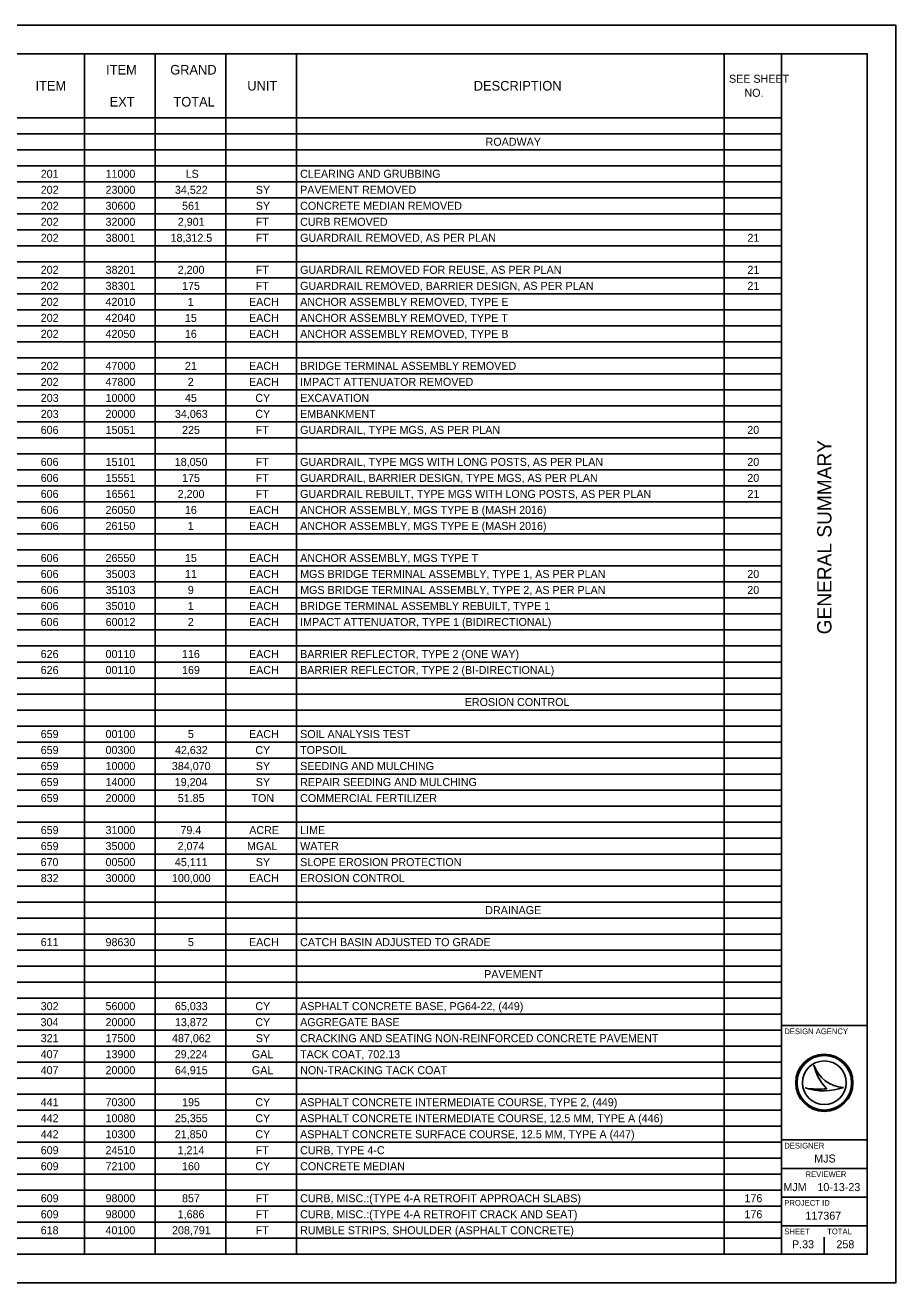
# Model space of a CAD drawing. Extents: x 0 to 34, y 0 to 22.
# Drawn here: x 18.78 to 34, y 0 to 22 of the extents above; entities that cross this region are included whole.
import ezdxf

# ---------------------------------------------------------------- set-up
doc = ezdxf.new("R2010")
doc.units = 0
for name, color, linetype in [('Default', 7, 'Continuous'), ('SH_Border', 7, 'Continuous'), ('SH_Cut_Line', 7, 'Continuous'), ('SH_Data', 7, 'Continuous')]:
    doc.layers.add(name, color=color, linetype=linetype)

msp = doc.modelspace()

# ---------------------------------------------------------------- linework, layer by layer
at = {"layer": 'Default'}
for p, q in [((1.5, 21.5), (32.004, 21.5)), ((19.815, 21.5), (19.815, 0.5)), ((21.051, 21.5), (21.051, 0.5)), ((22.286, 21.5), (22.286, 0.5)), ((23.521, 21.5), (23.521, 0.5)), ((30.999, 21.5), (30.999, 0.5)), ((32.004, 21.5), (32.004, 0.5)), ((1.5, 20.38), (32.004, 20.38)), ((1.5, 20.1), (32.004, 20.1)), ((1.5, 19.82), (32.004, 19.82)), ((1.5, 19.54), (32.004, 19.54)), ((1.5, 19.26), (32.004, 19.26)), ((1.5, 18.98), (32.004, 18.98)), ((1.5, 18.7), (32.004, 18.7)), ((1.5, 18.42), (32.004, 18.42)), ((1.5, 18.14), (32.004, 18.14)), ((1.5, 17.86), (32.004, 17.86)), ((1.5, 17.58), (32.004, 17.58)), ((1.5, 17.3), (32.004, 17.3)), ((1.5, 17.02), (32.004, 17.02)), ((1.5, 16.74), (32.004, 16.74)), ((1.5, 16.46), (32.004, 16.46)), ((1.5, 16.18), (32.004, 16.18)), ((1.5, 15.9), (32.004, 15.9)), ((1.5, 15.62), (32.004, 15.62)), ((1.5, 15.34), (32.004, 15.34)), ((1.5, 15.06), (32.004, 15.06)), ((1.5, 14.78), (32.004, 14.78)), ((1.5, 14.5), (32.004, 14.5)), ((1.5, 14.22), (32.004, 14.22)), ((1.5, 13.94), (32.004, 13.94)), ((1.5, 13.66), (32.004, 13.66)), ((1.5, 13.38), (32.004, 13.38)), ((1.5, 13.1), (32.004, 13.1)), ((1.5, 12.82), (32.004, 12.82)), ((1.5, 12.54), (32.004, 12.54)), ((1.5, 12.26), (32.004, 12.26)), ((1.5, 11.98), (32.004, 11.98)), ((1.5, 11.7), (32.004, 11.7)), ((1.5, 11.42), (32.004, 11.42)), ((1.5, 11.14), (32.004, 11.14)), ((1.5, 10.86), (32.004, 10.86)), ((1.5, 10.58), (32.004, 10.58)), ((1.5, 10.3), (32.004, 10.3)), ((1.5, 10.02), (32.004, 10.02)), ((1.5, 9.74), (32.004, 9.74)), ((1.5, 9.46), (32.004, 9.46)), ((1.5, 9.18), (32.004, 9.18)), ((1.5, 8.9), (32.004, 8.9)), ((1.5, 8.62), (32.004, 8.62)), ((1.5, 8.34), (32.004, 8.34)), ((1.5, 8.06), (32.004, 8.06)), ((1.5, 7.78), (32.004, 7.78)), ((1.5, 7.5), (32.004, 7.5)), ((1.5, 7.22), (32.004, 7.22)), ((1.5, 6.94), (32.004, 6.94)), ((1.5, 6.66), (32.004, 6.66)), ((1.5, 6.38), (32.004, 6.38)), ((1.5, 6.1), (32.004, 6.1)), ((1.5, 5.82), (32.004, 5.82)), ((1.5, 5.54), (32.004, 5.54)), ((1.5, 5.26), (32.004, 5.26)), ((1.5, 4.98), (32.004, 4.98)), ((1.5, 4.7), (32.004, 4.7)), ((1.5, 4.42), (32.004, 4.42)), ((1.5, 4.14), (32.004, 4.14)), ((1.5, 3.86), (32.004, 3.86)), ((1.5, 3.58), (32.004, 3.58)), ((1.5, 3.3), (32.004, 3.3)), ((1.5, 3.02), (32.004, 3.02)), ((1.5, 2.74), (32.004, 2.74)), ((1.5, 2.46), (32.004, 2.46)), ((1.5, 2.18), (32.004, 2.18)), ((1.5, 1.9), (32.004, 1.9)), ((1.5, 1.62), (32.004, 1.62)), ((1.5, 1.34), (32.004, 1.34)), ((1.5, 1.06), (32.004, 1.06)), ((1.5, 0.78), (32.004, 0.78)), ((1.5, 0.5), (32.004, 0.5))]:
    msp.add_line(p, q, dxfattribs=at)
at = {"layer": 'SH_Border'}
for p, q in [((32, 0.5), (32, 21.5)), ((32, 4.5), (33.5, 4.5)), ((32, 2.5), (33.5, 2.5)), ((32, 2), (33.5, 2)), ((32, 1.5), (33.5, 1.5)), ((32, 1), (33.5, 1))]:
    msp.add_line(p, q, dxfattribs=at)
msp.add_lwpolyline([(1.5, 21.5), (33.5, 21.5), (33.5, 0.5), (1.5, 0.5)], close=True, dxfattribs=at)
at = {"layer": 'SH_Cut_Line'}
msp.add_lwpolyline([(0, 0), (34, 0), (34, 22), (0, 22)], close=True, dxfattribs=at)
at = {"layer": 'SH_Data'}
for p, q in [((32.567, 3.81), (32.567, 3.81)), ((32.417, 3.41), (32.417, 3.41)), ((32.75, 3.5), (32.75, 3.5)), ((33.087, 3.419), (33.087, 3.419)), ((32.375, 0.675), (32.375, 0.675)), ((32.75, 0.5), (32.75, 0.8))]:
    msp.add_line(p, q, dxfattribs=at)
for radius in [0.5, 0.477, 0.477, 0.382]:
    msp.add_circle((32.75, 3.5), radius, dxfattribs=at)
for centre, radius, start, end in [((33.116, 3.998), 0.58, 198.9257, 198.9319), ((33.347, 3.97), 0.796, 191.6379, 191.6421), ((33.116, 3.998), 0.58, 198.9319, 267.1657), ((33.347, 3.97), 0.796, 191.6421, 226.0947), ((32.739, 4.37), 1.013, 251.4576, 290.0832), ((32.648, 4.654), 1.266, 259.4964, 259.4995), ((32.739, 4.37), 1.013, 251.4527, 251.4576), ((32.648, 4.654), 1.266, 259.4995, 276.6672)]:
    msp.add_arc(centre, radius, start, end, dxfattribs=at)

# ---------------------------------------------------------------- texts
at = {"layer": 'Default'}
for s, height, p in [('ITEM', 0.168, (20.195, 21.136)), ('GRAND', 0.168, (21.315, 21.136)), ('SEE SHEET ', 0.14, (31.084, 20.992)), ('ITEM', 0.168, (18.96, 20.856)), ('UNIT', 0.168, (22.663, 20.856)), ('DESCRIPTION', 0.168, (26.622, 20.856)), ('EXT', 0.168, (20.256, 20.576)), ('TOTAL', 0.168, (21.371, 20.576)), ('NO.', 0.14, (31.354, 20.747)), ('ROADWAY', 0.14, (26.829, 19.89)), ('201', 0.14, (19.052, 19.33)), ('11000', 0.14, (20.185, 19.33)), ('LS', 0.14, (21.585, 19.33)), ('CLEARING AND GRUBBING', 0.14, (23.587, 19.33)), ('202', 0.14, (19.052, 19.05)), ('23000', 0.14, (20.185, 19.05)), ('34,522', 0.14, (21.398, 19.05)), ('SY', 0.14, (22.812, 19.05)), ('PAVEMENT REMOVED', 0.14, (23.587, 19.05)), ('202', 0.14, (19.052, 18.77)), ('30600', 0.14, (20.185, 18.77)), ('561', 0.14, (21.523, 18.77)), ('SY', 0.14, (22.812, 18.77)), ('CONCRETE MEDIAN REMOVED', 0.14, (23.587, 18.77)), ('202', 0.14, (19.052, 18.49)), ('32000', 0.14, (20.185, 18.49)), ('2,901', 0.14, (21.448, 18.49)), ('FT', 0.14, (22.81, 18.49)), ('CURB REMOVED', 0.14, (23.587, 18.49)), ('202', 0.14, (19.052, 18.21)), ('38001', 0.14, (20.187, 18.21)), ('18,312.5', 0.14, (21.322, 18.21)), ('FT', 0.14, (22.81, 18.21)), ('GUARDRAIL REMOVED, AS PER PLAN', 0.14, (23.587, 18.21)), ('21', 0.14, (31.406, 18.21)), ('202', 0.14, (19.052, 17.65)), ('38201', 0.14, (20.187, 17.65)), ('2,200', 0.14, (21.446, 17.65)), ('FT', 0.14, (22.81, 17.65)), ('GUARDRAIL REMOVED FOR REUSE, AS PER PLAN', 0.14, (23.587, 17.65)), ('21', 0.14, (31.406, 17.65)), ('202', 0.14, (19.052, 17.37)), ('38301', 0.14, (20.187, 17.37)), ('175', 0.14, (21.523, 17.37)), ('FT', 0.14, (22.81, 17.37)), ('GUARDRAIL REMOVED, BARRIER DESIGN, AS PER PLAN', 0.14, (23.587, 17.37)), ('21', 0.14, (31.406, 17.37)), ('202', 0.14, (19.052, 17.09)), ('42010', 0.14, (20.185, 17.09)), ('1', 0.14, (21.623, 17.09)), ('EACH', 0.14, (22.693, 17.09)), ('ANCHOR ASSEMBLY REMOVED, TYPE E', 0.14, (23.587, 17.09)), ('202', 0.14, (19.052, 16.81)), ('42040', 0.14, (20.185, 16.81)), ('15', 0.14, (21.573, 16.81)), ('EACH', 0.14, (22.693, 16.81)), ('ANCHOR ASSEMBLY REMOVED, TYPE T', 0.14, (23.587, 16.81)), ('202', 0.14, (19.052, 16.53)), ('42050', 0.14, (20.185, 16.53)), ('16', 0.14, (21.572, 16.53)), ('EACH', 0.14, (22.693, 16.53)), ('ANCHOR ASSEMBLY REMOVED, TYPE B', 0.14, (23.587, 16.53)), ('202', 0.14, (19.052, 15.97)), ('47000', 0.14, (20.185, 15.97)), ('21', 0.14, (21.573, 15.97)), ('EACH', 0.14, (22.693, 15.97)), ('BRIDGE TERMINAL ASSEMBLY REMOVED', 0.14, (23.587, 15.97)), ('202', 0.14, (19.052, 15.69)), ('47800', 0.14, (20.185, 15.69)), ('2', 0.14, (21.623, 15.69)), ('EACH', 0.14, (22.693, 15.69)), ('IMPACT ATTENUATOR REMOVED', 0.14, (23.587, 15.69)), ('203', 0.14, (19.053, 15.41)), ('10000', 0.14, (20.185, 15.41)), ('45', 0.14, (21.573, 15.41)), ('CY', 0.14, (22.804, 15.41)), ('EXCAVATION', 0.14, (23.587, 15.41)), ('203', 0.14, (19.053, 15.13)), ('20000', 0.14, (20.185, 15.13)), ('34,063', 0.14, (21.398, 15.13)), ('CY', 0.14, (22.804, 15.13)), ('EMBANKMENT', 0.14, (23.587, 15.13)), ('606', 0.14, (19.051, 14.85)), ('15051', 0.14, (20.187, 14.85)), ('225', 0.14, (21.523, 14.85)), ('FT', 0.14, (22.81, 14.85)), ('GUARDRAIL, TYPE MGS, AS PER PLAN', 0.14, (23.587, 14.85)), ('20', 0.14, (31.404, 14.85)), ('606', 0.14, (19.051, 14.29)), ('15101', 0.14, (20.187, 14.29)), ('18,050', 0.14, (21.395, 14.29)), ('FT', 0.14, (22.81, 14.29)), ('GUARDRAIL, TYPE MGS WITH LONG POSTS, AS PER PLAN', 0.14, (23.587, 14.29)), ('20', 0.14, (31.404, 14.29)), ('606', 0.14, (19.051, 14.01)), ('15551', 0.14, (20.187, 14.01)), ('175', 0.14, (21.523, 14.01)), ('FT', 0.14, (22.81, 14.01)), ('GUARDRAIL, BARRIER DESIGN, TYPE MGS, AS PER PLAN', 0.14, (23.587, 14.01)), ('20', 0.14, (31.404, 14.01)), ('606', 0.14, (19.051, 13.73)), ('16561', 0.14, (20.187, 13.73)), ('2,200', 0.14, (21.446, 13.73)), ('FT', 0.14, (22.81, 13.73)), ('GUARDRAIL REBUILT, TYPE MGS WITH LONG POSTS, AS PER PLAN', 0.14, (23.587, 13.73)), ('21', 0.14, (31.406, 13.73)), ('606', 0.14, (19.051, 13.45)), ('26050', 0.14, (20.185, 13.45)), ('16', 0.14, (21.572, 13.45)), ('EACH', 0.14, (22.693, 13.45)), ('ANCHOR ASSEMBLY, MGS TYPE B (MASH 2016)', 0.14, (23.587, 13.45)), ('606', 0.14, (19.051, 13.17)), ('26150', 0.14, (20.185, 13.17)), ('1', 0.14, (21.623, 13.17)), ('EACH', 0.14, (22.693, 13.17)), ('ANCHOR ASSEMBLY, MGS TYPE E (MASH 2016)', 0.14, (23.587, 13.17)), ('606', 0.14, (19.051, 12.61)), ('26550', 0.14, (20.185, 12.61)), ('15', 0.14, (21.573, 12.61)), ('EACH', 0.14, (22.693, 12.61)), ('ANCHOR ASSEMBLY, MGS TYPE T', 0.14, (23.587, 12.61)), ('606', 0.14, (19.051, 12.33)), ('35003', 0.14, (20.188, 12.33)), ('11', 0.14, (21.573, 12.33)), ('EACH', 0.14, (22.693, 12.33)), ('MGS BRIDGE TERMINAL ASSEMBLY, TYPE 1, AS PER PLAN', 0.14, (23.587, 12.33)), ('20', 0.14, (31.404, 12.33)), ('606', 0.14, (19.051, 12.05)), ('35103', 0.14, (20.188, 12.05)), ('9', 0.14, (21.623, 12.05)), ('EACH', 0.14, (22.693, 12.05)), ('MGS BRIDGE TERMINAL ASSEMBLY, TYPE 2, AS PER PLAN', 0.14, (23.587, 12.05)), ('20', 0.14, (31.404, 12.05)), ('606', 0.14, (19.051, 11.77)), ('35010', 0.14, (20.185, 11.77)), ('1', 0.14, (21.623, 11.77)), ('EACH', 0.14, (22.693, 11.77)), ('BRIDGE TERMINAL ASSEMBLY REBUILT, TYPE 1', 0.14, (23.587, 11.77)), ('606', 0.14, (19.051, 11.49)), ('60012', 0.14, (20.187, 11.49)), ('2', 0.14, (21.623, 11.49)), ('EACH', 0.14, (22.693, 11.49)), ('IMPACT ATTENUATOR, TYPE 1 (BIDIRECTIONAL)', 0.14, (23.587, 11.49)), ('626', 0.14, (19.051, 10.93)), ('00110', 0.14, (20.185, 10.93)), ('116', 0.14, (21.521, 10.93)), ('EACH', 0.14, (22.693, 10.93)), ('BARRIER REFLECTOR, TYPE 2 (ONE WAY)', 0.14, (23.587, 10.93)), ('626', 0.14, (19.051, 10.65)), ('00110', 0.14, (20.185, 10.65)), ('169', 0.14, (21.522, 10.65)), ('EACH', 0.14, (22.693, 10.65)), ('BARRIER REFLECTOR, TYPE 2 (BI-DIRECTIONAL)', 0.14, (23.587, 10.65)), ('EROSION CONTROL', 0.14, (26.464, 10.09)), ('659', 0.14, (19.052, 9.53)), ('00100', 0.14, (20.185, 9.53)), ('5', 0.14, (21.624, 9.53)), ('EACH', 0.14, (22.693, 9.53)), ('SOIL ANALYSIS TEST', 0.14, (23.587, 9.53)), ('659', 0.14, (19.052, 9.25)), ('00300', 0.14, (20.185, 9.25)), ('42,632', 0.14, (21.398, 9.25)), ('CY', 0.14, (22.804, 9.25)), ('TOPSOIL', 0.14, (23.587, 9.25)), ('659', 0.14, (19.052, 8.97)), ('10000', 0.14, (20.185, 8.97)), ('384,070', 0.14, (21.345, 8.97)), ('SY', 0.14, (22.812, 8.97)), ('SEEDING AND MULCHING', 0.14, (23.587, 8.97)), ('659', 0.14, (19.052, 8.69)), ('14000', 0.14, (20.185, 8.69)), ('19,204', 0.14, (21.395, 8.69)), ('SY', 0.14, (22.812, 8.69)), ('REPAIR SEEDING AND MULCHING', 0.14, (23.587, 8.69)), ('659', 0.14, (19.052, 8.41)), ('20000', 0.14, (20.185, 8.41)), ('51.85', 0.14, (21.448, 8.41)), ('TON', 0.14, (22.737, 8.41)), ('COMMERCIAL FERTILIZER', 0.14, (23.587, 8.41)), ('659', 0.14, (19.052, 7.85)), ('31000', 0.14, (20.185, 7.85)), ('79.4', 0.14, (21.495, 7.85)), ('ACRE', 0.14, (22.697, 7.85)), ('LIME', 0.14, (23.587, 7.85)), ('659', 0.14, (19.052, 7.57)), ('35000', 0.14, (20.185, 7.57)), ('2,074', 0.14, (21.445, 7.57)), ('MGAL', 0.14, (22.658, 7.57)), ('WATER', 0.14, (23.587, 7.57)), ('670', 0.14, (19.05, 7.29)), ('00500', 0.14, (20.185, 7.29)), ('45,111', 0.14, (21.397, 7.29)), ('SY', 0.14, (22.812, 7.29)), ('SLOPE EROSION PROTECTION', 0.14, (23.587, 7.29)), ('832', 0.14, (19.052, 7.01)), ('30000', 0.14, (20.185, 7.01)), ('100,000', 0.14, (21.345, 7.01)), ('EACH', 0.14, (22.693, 7.01)), ('EROSION CONTROL', 0.14, (23.587, 7.01)), ('DRAINAGE', 0.14, (26.823, 6.45)), ('611', 0.14, (19.052, 5.89)), ('98630', 0.14, (20.185, 5.89)), ('5', 0.14, (21.624, 5.89)), ('EACH', 0.14, (22.693, 5.89)), ('CATCH BASIN ADJUSTED TO GRADE', 0.14, (23.587, 5.89)), ('PAVEMENT', 0.14, (26.803, 5.33)), ('302', 0.14, (19.052, 4.77)), ('56000', 0.14, (20.185, 4.77)), ('65,033', 0.14, (21.398, 4.77)), ('CY', 0.14, (22.804, 4.77)), ('ASPHALT CONCRETE BASE, PG64-22, (449)', 0.14, (23.587, 4.77)), ('304', 0.14, (19.05, 4.49)), ('20000', 0.14, (20.185, 4.49)), ('13,872', 0.14, (21.398, 4.49)), ('CY', 0.14, (22.804, 4.49)), ('AGGREGATE BASE', 0.14, (23.587, 4.49)), ('321', 0.14, (19.052, 4.21)), ('17500', 0.14, (20.185, 4.21)), ('487,062', 0.14, (21.347, 4.21)), ('SY', 0.14, (22.812, 4.21)), ('CRACKING AND SEATING NON-REINFORCED CONCRETE PAVEMENT', 0.14, (23.587, 4.21)), ('407', 0.14, (19.051, 3.93)), ('13900', 0.14, (20.185, 3.93)), ('29,224', 0.14, (21.395, 3.93)), ('GAL', 0.14, (22.743, 3.93)), ('TACK COAT, 702.13', 0.14, (23.587, 3.93)), ('407', 0.14, (19.051, 3.65)), ('20000', 0.14, (20.185, 3.65)), ('64,915', 0.14, (21.398, 3.65)), ('GAL', 0.14, (22.743, 3.65)), ('NON-TRACKING TACK COAT', 0.14, (23.587, 3.65)), ('441', 0.14, (19.052, 3.09)), ('70300', 0.14, (20.185, 3.09)), ('195', 0.14, (21.523, 3.09)), ('CY', 0.14, (22.804, 3.09)), ('ASPHALT CONCRETE INTERMEDIATE COURSE, TYPE 2, (449)', 0.14, (23.587, 3.09)), ('442', 0.14, (19.052, 2.81)), ('10080', 0.14, (20.185, 2.81)), ('25,355', 0.14, (21.398, 2.81)), ('CY', 0.14, (22.804, 2.81)), ('ASPHALT CONCRETE INTERMEDIATE COURSE, 12.5 MM, TYPE A (446)', 0.14, (23.587, 2.81)), ('442', 0.14, (19.052, 2.53)), ('10300', 0.14, (20.185, 2.53)), ('21,850', 0.14, (21.395, 2.53)), ('CY', 0.14, (22.804, 2.53)), ('ASPHALT CONCRETE SURFACE COURSE, 12.5 MM, TYPE A (447)', 0.14, (23.587, 2.53)), ('609', 0.14, (19.052, 2.25)), ('24510', 0.14, (20.185, 2.25)), ('1,214', 0.14, (21.445, 2.25)), ('FT', 0.14, (22.81, 2.25)), ('CURB, TYPE 4-C', 0.14, (23.587, 2.25)), ('609', 0.14, (19.052, 1.97)), ('72100', 0.14, (20.185, 1.97)), ('160', 0.14, (21.521, 1.97)), ('CY', 0.14, (22.804, 1.97)), ('CONCRETE MEDIAN', 0.14, (23.587, 1.97)), ('609', 0.14, (19.052, 1.41)), ('98000', 0.14, (20.185, 1.41)), ('857', 0.14, (21.522, 1.41)), ('FT', 0.14, (22.81, 1.41)), ('CURB, MISC.:(TYPE 4-A RETROFIT APPROACH SLABS)', 0.14, (23.587, 1.41)), ('176', 0.14, (31.354, 1.41)), ('609', 0.14, (19.052, 1.13)), ('98000', 0.14, (20.185, 1.13)), ('1,686', 0.14, (21.446, 1.13)), ('FT', 0.14, (22.81, 1.13)), ('CURB, MISC.:(TYPE 4-A RETROFIT CRACK AND SEAT)', 0.14, (23.587, 1.13)), ('176', 0.14, (31.354, 1.13)), ('618', 0.14, (19.051, 0.85)), ('40100', 0.14, (20.185, 0.85)), ('208,791', 0.14, (21.347, 0.85)), ('FT', 0.14, (22.81, 0.85)), ('RUMBLE STRIPS, SHOULDER (ASPHALT CONCRETE)', 0.14, (23.587, 0.85))]:
    msp.add_text(s, height=height, dxfattribs=at).set_placement(p)
at = {"layer": 'SH_Data'}
msp.add_text('GENERAL SUMMARY', height=0.25, rotation=90, dxfattribs=at).set_placement((32.875, 11.344))
for s, height, p in [('DESIGN AGENCY', 0.1, (32.05, 4.35)), ('DESIGNER', 0.1, (32.05, 2.35)), ('MJS', 0.14, (32.574, 2.105)), ('REVIEWER', 0.1, (32.422, 1.85)), ('MJM', 0.14, (32.035, 1.605)), ('10-13-23', 0.14, (32.629, 1.605)), ('PROJECT ID', 0.1, (32.05, 1.35)), ('117367', 0.14, (32.42, 1.105)), ('SHEET', 0.1, (32.05, 0.85)), ('TOTAL', 0.1, (32.8, 0.85)), ('P.33', 0.14, (32.185, 0.605)), ('258', 0.14, (32.962, 0.605))]:
    msp.add_text(s, height=height, dxfattribs=at).set_placement(p)

doc.saveas('drawing.dxf')
